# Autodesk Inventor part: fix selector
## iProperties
Created: 2006-04
Part Number: fix selector
Document SubType Name: Modeling
Designer: Калинин
Author: Калинин
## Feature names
1. Сдвиг1
2. Сопряжение1 [Fillet]
3. Сопряжение2 [Fillet]
